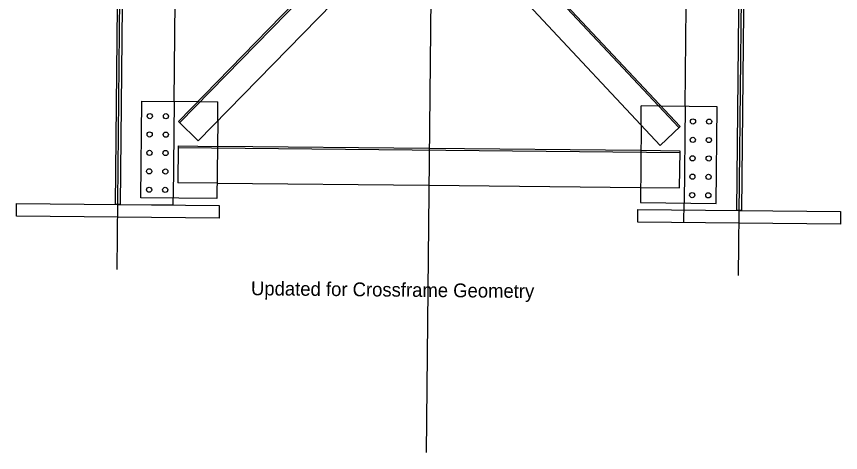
# Model space of a CAD drawing. Extents: x 632312 to 632885, y 378199 to 378534.
# Drawn here: x 632391.35 to 632406.27, y 378378.62 to 378386.51 of the extents above; entities that cross this region are included whole.
import ezdxf

# ---------------------------------------------------------------- set-up
doc = ezdxf.new("R2010")
doc.units = 0
for name, color, linetype in [('B_Boring', 7, 'Continuous'), ('R_Proposed Const Limits Cut', 7, 'Continuous'), ('R_Road Edge of Shoulder', 7, 'Continuous'), ('R_Shade Removal', 7, 'Continuous'), ('SHT_Dimensions', 7, 'Continuous')]:
    doc.layers.add(name, color=color, linetype=linetype)

msp = doc.modelspace()

# ---------------------------------------------------------------- linework, layer by layer
at = {"layer": 'B_Boring'}
for p, q in [((632403.457, 378384.887), (632403.475, 378386.695)), ((632394.287, 378384.614), (632394.645, 378384.265)), ((632403.37, 378384.524), (632403.005, 378384.182)), ((632398.824, 378384.125), (632394.991, 378384.163)), ((632402.657, 378384.087), (632398.824, 378384.125)), ((632394.984, 378383.497), (632398.817, 378383.459)), ((632398.817, 378383.459), (632402.651, 378383.421)), ((632403.436, 378382.787), (632403.44, 378383.137))]:
    msp.add_line(p, q, dxfattribs=at)
for points in [[(632393.23, 378383.113), (632393.147, 378383.114), (632393.266, 378395.114), (632393.35, 378395.113)], [(632404.48, 378383.002), (632404.397, 378383.002), (632404.516, 378395.002), (632404.599, 378395.001)], [(632395.022, 378383.096), (632395.02, 378382.866), (632391.353, 378382.903), (632391.356, 378383.132)], [(632406.271, 378382.984), (632406.269, 378382.755), (632402.603, 378382.791), (632402.605, 378383.02)]]:
    msp.add_lwpolyline(points, close=True, dxfattribs=at)
for points in [[(632394.306, 378394.904), (632394.308, 378395.103), (632393.35, 378395.113), (632393.23, 378383.113), (632394.189, 378383.104), (632394.19, 378383.229)], [(632394.207, 378384.979), (632394.225, 378386.787)], [(632396.388, 378386.765), (632394.287, 378384.614)], [(632394.645, 378384.265), (632397.08, 378386.758)], [(632403.005, 378384.182), (632400.62, 378386.723)], [(632401.313, 378386.716), (632403.37, 378384.524)], [(632394.996, 378384.624), (632394.982, 378383.221), (632394.982, 378383.221), (632394.982, 378383.221), (632393.607, 378383.235), (632393.624, 378384.985), (632394.639, 378384.975)], [(632402.662, 378384.548), (632402.648, 378383.145), (632402.648, 378383.145), (632402.648, 378383.145), (632404.023, 378383.131), (632404.04, 378384.881), (632403.026, 378384.891)]]:
    msp.add_lwpolyline(points, dxfattribs=at)
for centre in [(632393.767, 378384.712), (632394.059, 378384.709), (632403.6, 378384.615), (632403.892, 378384.612), (632393.764, 378384.379), (632394.056, 378384.376), (632403.597, 378384.281), (632403.888, 378384.278), (632393.761, 378384.046), (632394.052, 378384.043), (632403.593, 378383.948), (632403.885, 378383.945), (632393.757, 378383.712), (632394.049, 378383.709), (632403.59, 378383.615), (632403.882, 378383.612), (632393.754, 378383.379), (632394.046, 378383.376), (632403.587, 378383.281), (632403.878, 378383.278)]:
    msp.add_circle(centre, 0.0469, dxfattribs=at)
at = {"layer": 'R_Proposed Const Limits Cut'}
for p, q in [((632394.716, 378393.699), (632403.347, 378384.503)), ((632403.122, 378393.615), (632394.309, 378384.593)), ((632394.207, 378384.979), (632394.19, 378383.229)), ((632394.639, 378384.975), (632394.999, 378384.971)), ((632394.996, 378384.624), (632394.999, 378384.971)), ((632402.662, 378384.548), (632402.665, 378384.895)), ((632403.026, 378384.891), (632402.665, 378384.895)), ((632403.457, 378384.887), (632403.44, 378383.137)), ((632394.283, 378384.171), (632394.276, 378383.504)), ((632403.365, 378384.049), (632394.282, 378384.139)), ((632394.283, 378384.171), (632394.991, 378384.163)), ((632403.366, 378384.08), (632402.657, 378384.087)), ((632403.359, 378383.414), (632403.366, 378384.08)), ((632394.984, 378383.497), (632394.276, 378383.504)), ((632402.651, 378383.421), (632403.359, 378383.414))]:
    msp.add_line(p, q, dxfattribs=at)
at = {"layer": 'R_Road Edge of Shoulder'}
msp.add_line((632398.776, 378378.623), (632399.106, 378411.8), dxfattribs=at)
at = {"layer": 'R_Shade Removal'}
for p, q in [((632393.177, 378381.937), (632393.327, 378397.002)), ((632404.427, 378381.825), (632404.576, 378396.89))]:
    msp.add_line(p, q, dxfattribs=at)

# ---------------------------------------------------------------- texts
at = {"layer": 'SHT_Dimensions'}
msp.add_text('Updated for Crossframe Geometry', height=0.25, rotation=359.4304, dxfattribs=at).set_placement((632395.598, 378381.47))

doc.saveas('drawing.dxf')
